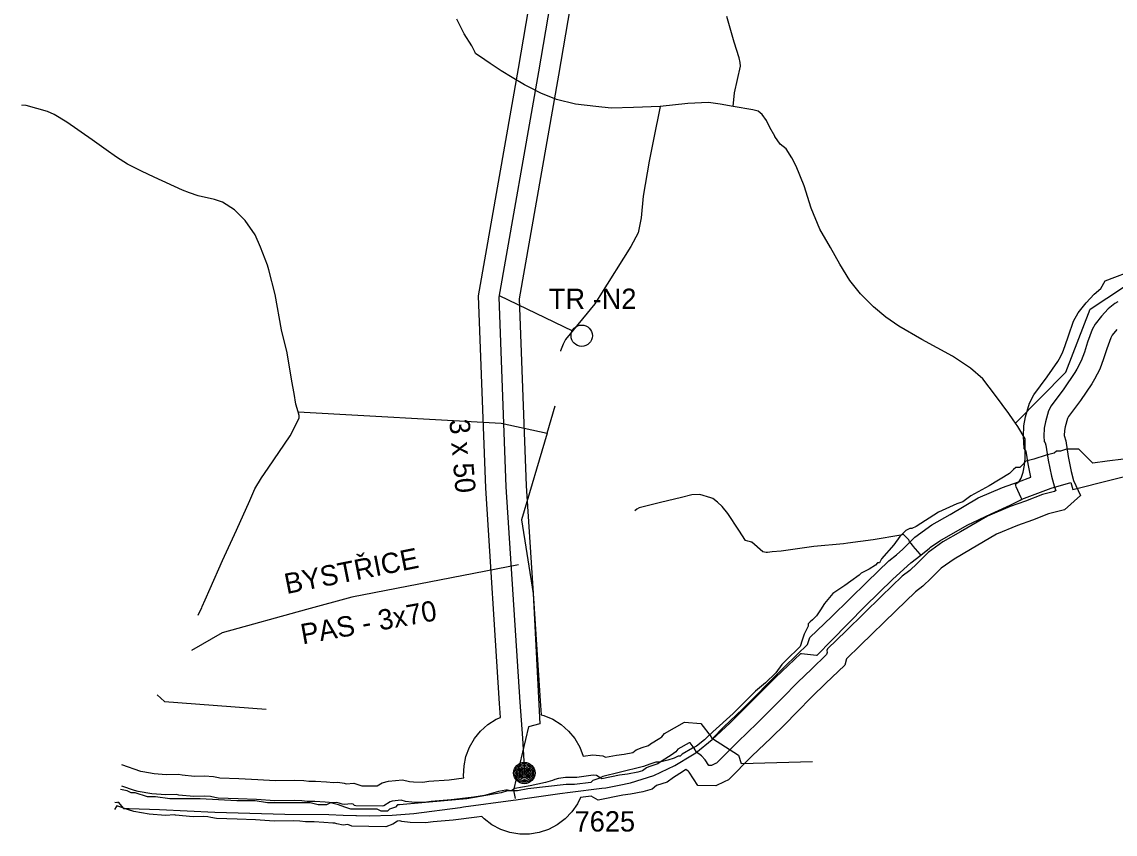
# Model space of a CAD drawing. Extents: x -439095 to -431527, y -1129525 to -1119219.
# Drawn here: x -438699 to -438161, y -1124403 to -1124004 of the extents above; entities that cross this region are included whole.
import ezdxf

# ---------------------------------------------------------------- set-up
doc = ezdxf.new("R2010")
doc.units = 0
for name, color, linetype in [('Hranice reseneho uzemi', 7, 'Continuous'), ('UZEMNI REZERVA', 7, 'Continuous'), ('Vrstva 11', 7, 'Continuous'), ('Vrstva 13', 7, 'Continuous'), ('Vrstva 19', 7, 'Continuous'), ('Vrstva 21', 7, 'Continuous'), ('Vrstva 58', 7, 'Continuous'), ('ZU', 7, 'Continuous')]:
    doc.layers.add(name, color=color, linetype=linetype)

msp = doc.modelspace()

# ---------------------------------------------------------------- linework, layer by layer
at = {"layer": 'Hranice reseneho uzemi'}
msp.add_line((-438464.02, -1124138.56), (-438428.03, -1124155.83), dxfattribs=at)
for points in [[(-438404.4, -1123792.3), (-438410.29, -1123829.14), (-438410.29, -1123829.15), (-438415.85, -1123861.97), (-438429.64, -1123939.97), (-438444.63, -1124028.49), (-438464.17, -1124139.38), (-438460.66, -1124232.64), (-438453.88, -1124338.49), (-438452.62, -1124356.08), (-438452.62, -1124356.09), (-438451.55, -1124372.99), (-438451.29, -1124373.35), (-438451.28, -1124373.5)], [(-438159.73, -1124141.57), (-438161.25, -1124142.38), (-438164.49, -1124145.06), (-438167.77, -1124148.6), (-438170.88, -1124152.51), (-438172.35, -1124155.27), (-438174.63, -1124161.5), (-438176.19, -1124166.38), (-438177.78, -1124170.67), (-438179.87, -1124174.71), (-438180.94, -1124176.42), (-438186.35, -1124184.31), (-438192.5, -1124192.7), (-438193.83, -1124195.21), (-438195.39, -1124200.58), (-438196.05, -1124203.67), (-438196.14, -1124207.6), (-438196, -1124210.23), (-438195.48, -1124210.94), (-438195.17, -1124212.06), (-438194.07, -1124219.42), (-438192.42, -1124227.33), (-438190.97, -1124232.78), (-438190.27, -1124234.31), (-438190.84, -1124234.82), (-438196.86, -1124236.34), (-438205.18, -1124239.55), (-438212.77, -1124242.22), (-438223.88, -1124246.96), (-438237.2, -1124254.75), (-438245.75, -1124259.66), (-438253.08, -1124264.93), (-438258.48, -1124270.33), (-438262.11, -1124273.73), (-438265.86, -1124276.55), (-438275.98, -1124286.4), (-438293.42, -1124303.41), (-438302.55, -1124312.28), (-438302.85, -1124313.1), (-438302.75, -1124314.02), (-438303, -1124314.98), (-438310.44, -1124322.14), (-438317.11, -1124328.6), (-438324.91, -1124336.52), (-438330.52, -1124342.17), (-438337.21, -1124348.83), (-438346.69, -1124357.9), (-438357.18, -1124368.4), (-438357.68, -1124368.64), (-438359.64, -1124369.6), (-438360.85, -1124369.58), (-438362.64, -1124366.81), (-438364.44, -1124364.77), (-438367.02, -1124363), (-438368.14, -1124361.12), (-438370.1, -1124358.5), (-438370.65, -1124358.46), (-438376.19, -1124361.59), (-438377.2, -1124362.79), (-438379.44, -1124364.45), (-438383.91, -1124367.24), (-438386.01, -1124368.79), (-438390.35, -1124370.16), (-438391.64, -1124370.67), (-438393.5, -1124372.16), (-438395.77, -1124372.84), (-438400.98, -1124373.87), (-438404.78, -1124374.31), (-438413.55, -1124376.09), (-438416.19, -1124374.51), (-438417.72, -1124374.37), (-438425.81, -1124375.5), (-438431.39, -1124375.53), (-438434.79, -1124375.92), (-438436.57, -1124376.42), (-438437.82, -1124377.04), (-438441.25, -1124377.9), (-438448.75, -1124379.6), (-438456.35, -1124380.91), (-438457.34, -1124381.58), (-438458.27, -1124382), (-438459.05, -1124381.94), (-438459.93, -1124381.67), (-438460.8, -1124381.66), (-438464.27, -1124382.33), (-438471.29, -1124384.36), (-438476.45, -1124385.16), (-438487.66, -1124386.53), (-438497.5, -1124387.28), (-438500.94, -1124387.74), (-438506.98, -1124387.67), (-438510.02, -1124387.25), (-438512.21, -1124386.7), (-438516.63, -1124387.2), (-438517.67, -1124387.47), (-438520.81, -1124389.41), (-438521.48, -1124389.66), (-438534.53, -1124389.49), (-438535.1, -1124389.26), (-438535.86, -1124388.65), (-438536.57, -1124388.43), (-438540.18, -1124388.78), (-438541.24, -1124388.54), (-438542.67, -1124388.07), (-438544.02, -1124387.84), (-438545.68, -1124387.9), (-438549.62, -1124387.61), (-438554.7, -1124387.34), (-438558.49, -1124387.33), (-438561.04, -1124386.93), (-438564.88, -1124386.78), (-438574.41, -1124386.96), (-438583.31, -1124386.37), (-438592.42, -1124385.91), (-438602.2, -1124385.64), (-438603.89, -1124385.39), (-438605.95, -1124384.9), (-438609.15, -1124384.74), (-438614.19, -1124384.76), (-438621.57, -1124384.15), (-438622.77, -1124383.86), (-438627.88, -1124384.09), (-438634.89, -1124383.53), (-438641.48, -1124382.36), (-438643.3, -1124381.86), (-438649.51, -1124379.72)], [(-438454.46, -1124270.9), (-438536.54, -1124286.77), (-438558.76, -1124292.96), (-438600.22, -1124304.31), (-438615.26, -1124312.96)]]:
    msp.add_lwpolyline(points, dxfattribs=at)
at = {"layer": 'UZEMNI REZERVA'}
for points in [[(-438348.9, -1124045.54), (-438355.36, -1124044.32), (-438361.03, -1124043.62), (-438371.16, -1124044.13), (-438384.78, -1124045.52), (-438397.98, -1124046.07), (-438408.99, -1124046.3), (-438416.44, -1124045.57), (-438426.48, -1124044.41), (-438435.87, -1124042.12), (-438443.49, -1124039.07), (-438449.57, -1124035.89), (-438451.55, -1124034.86), (-438457.67, -1124031.28), (-438463.03, -1124027.93), (-438467.95, -1124024.69), (-438468.49, -1124024.39), (-438471.13, -1124022.54), (-438475.63, -1124019.41), (-438475.9, -1124019), (-438476.32, -1124018), (-438477.44, -1124015.75), (-438481.23, -1124009.81), (-438484.76, -1124002.63)], [(-438206.98, -1124238.63), (-438207.31, -1124237.99), (-438209.68, -1124232.52), (-438210.03, -1124231.18), (-438208.35, -1124229.88), (-438207.24, -1124228.28), (-438206.27, -1124225.31), (-438205.6, -1124221.87), (-438205.39, -1124218.59), (-438205.38, -1124208.91), (-438208.95, -1124202.9), (-438211.18, -1124199.65), (-438213.44, -1124196.43), (-438219.91, -1124187.58), (-438226.22, -1124179.51), (-438232.16, -1124174.16), (-438241.15, -1124168.29), (-438256.12, -1124160.13), (-438267.39, -1124153.52), (-438273.87, -1124149.16), (-438279.88, -1124144.09), (-438286.38, -1124137.63), (-438291.57, -1124131.18), (-438296.51, -1124123.05), (-438301.01, -1124114.91), (-438306.3, -1124105.84), (-438310.53, -1124095.5), (-438313.97, -1124084.49), (-438317.97, -1124074.85), (-438320.09, -1124070.82), (-438322.85, -1124066.3), (-438325.76, -1124064.1), (-438328.43, -1124060.25), (-438328.45, -1124060.2), (-438328.48, -1124060.12), (-438330.86, -1124055.87), (-438332.48, -1124052.42), (-438334.63, -1124049.45), (-438336.71, -1124047.81), (-438339.25, -1124047.18), (-438348.9, -1124045.54), (-438348.28, -1124038.89), (-438345.38, -1124025.67), (-438345.49, -1124023.85), (-438345.92, -1124021.55), (-438348.43, -1124013.96), (-438352.09, -1124001.36)], [(-438611.98, -1124295.6), (-438611.01, -1124293.59), (-438610.3, -1124292.13), (-438610.02, -1124291.46), (-438608.61, -1124288.18), (-438606.17, -1124282.5), (-438600.02, -1124268.85), (-438593.18, -1124253.8), (-438586.66, -1124239.25), (-438584.12, -1124233.54), (-438580.97, -1124228.1), (-438577.55, -1124223.36), (-438566.79, -1124207.47), (-438562.46, -1124198.79), (-438562.34, -1124197.5), (-438562.81, -1124195.62), (-438563.95, -1124191.94), (-438564.89, -1124186.64), (-438565.95, -1124180.62), (-438568.31, -1124166.74), (-438571.02, -1124155.36), (-438574.11, -1124137.91), (-438577.28, -1124125.87), (-438577.88, -1124123.63), (-438581.44, -1124114.68), (-438584.01, -1124108.57), (-438588.98, -1124101.68), (-438594.14, -1124096.42), (-438600.12, -1124092.65), (-438604, -1124091.32), (-438611.99, -1124089.41), (-438616.32, -1124088), (-438619.76, -1124086.64), (-438633.77, -1124080.35), (-438639.91, -1124077.33), (-438646.77, -1124073.88), (-438652.27, -1124070.47), (-438657.36, -1124066.91), (-438664.23, -1124061.87), (-438676.61, -1124053.33), (-438682.81, -1124049.48), (-438686.13, -1124048.03), (-438696.57, -1124044.98), (-438698.73, -1124044.93), (-438698.75, -1124045.09)], [(-438384.78, -1124045.52), (-438388.19, -1124061.8), (-438390.22, -1124072.41), (-438393.2, -1124089.61), (-438394.14, -1124100.33), (-438395.74, -1124107.6), (-438399.34, -1124114.39), (-438414.52, -1124138.69), (-438416.92, -1124142.58), (-438431.45, -1124160.06), (-438432.62, -1124162.43), (-438433.86, -1124165.7), (-438433.84, -1124165.88)], [(-438210.06, -1124201.28), (-438185.4, -1124176.11), (-438173.41, -1124145.17), (-438156.99, -1124134.43), (-438095.98, -1124117.57)], [(-438562.81, -1124195.62), (-438463.1, -1124201.21), (-438440.37, -1124206.25), (-438436.53, -1124192.7)], [(-438440.37, -1124206.25), (-438453.11, -1124248.71), (-438447.29, -1124284.97), (-438443.96, -1124349.11), (-438449.54, -1124350.56), (-438456.94, -1124381.69), (-438456.2, -1124385.75)], [(-438653.02, -1124387.55), (-438651.91, -1124387.71), (-438651.67, -1124387.53), (-438651.46, -1124387.63), (-438648.8, -1124390.79), (-438646.01, -1124390.78), (-438631.05, -1124391.27), (-438603.82, -1124392.47), (-438569.46, -1124393.49), (-438547.87, -1124393.68), (-438540.72, -1124393.94), (-438534.45, -1124394.17), (-438534.19, -1124394.18), (-438528, -1124394.41), (-438516.72, -1124394.05), (-438505.99, -1124393.22), (-438483.22, -1124390.22), (-438481.54, -1124389.99), (-438457.2, -1124386.65), (-438455.64, -1124386.43), (-438452.59, -1124386), (-438434.26, -1124383.43), (-438429.15, -1124382.78), (-438413.51, -1124380.77), (-438411.63, -1124380.53), (-438405.01, -1124379.2), (-438399.39, -1124378.07), (-438387.96, -1124374.57), (-438377.57, -1124369.59), (-438368.91, -1124364.39), (-438367.27, -1124363.39), (-438359.31, -1124356.82), (-438350.39, -1124348.68), (-438329.27, -1124327.48), (-438328.12, -1124326.33), (-438315.69, -1124314.48), (-438315.29, -1124314.52), (-438308, -1124315.36), (-438307.67, -1124315.37), (-438300.65, -1124308.18), (-438284.26, -1124291.39), (-438270.47, -1124278.01), (-438261.49, -1124269.93), (-438256.66, -1124266.09), (-438252.43, -1124262.73), (-438251.88, -1124262.29), (-438247.26, -1124259.15), (-438233.92, -1124251.4), (-438222.01, -1124245.82), (-438212.65, -1124241.53), (-438207.77, -1124239.1), (-438206.98, -1124238.63), (-438192.51, -1124233.19), (-438182.87, -1124230.5), (-438181.97, -1124233.91), (-438144.24, -1124224.41)], [(-438256.66, -1124266.09), (-438256.98, -1124265.67), (-438260.37, -1124261.73), (-438260.5, -1124261.56), (-438260.62, -1124261.39), (-438260.77, -1124261.19), (-438262.14, -1124259.37), (-438262.34, -1124259.06), (-438262.45, -1124258.88), (-438262.57, -1124258.7), (-438264.3, -1124256.85), (-438265.18, -1124255.95), (-438266.51, -1124256.26), (-438280.11, -1124258.65), (-438292.59, -1124260.24), (-438294.75, -1124260.52), (-438309.24, -1124261.97), (-438325.35, -1124264.22), (-438329.8, -1124264.58), (-438332.08, -1124264.88), (-438332.78, -1124264.77), (-438334.34, -1124264.53), (-438339.73, -1124259.85), (-438339.86, -1124259.75), (-438340.39, -1124259.62), (-438341.72, -1124259.28), (-438342.88, -1124258.88), (-438346.22, -1124253.89), (-438351.6, -1124245.66), (-438354.34, -1124242.29), (-438356.62, -1124240.09), (-438358.91, -1124238.37), (-438359.86, -1124238.03), (-438365.3, -1124236.38), (-438369.28, -1124236.43), (-438374.42, -1124237.73), (-438384.75, -1124240.22), (-438395.24, -1124242.92), (-438396.36, -1124243.52), (-438397.23, -1124244.3)], [(-438632.18, -1124334.88), (-438628.53, -1124338.06), (-438578.66, -1124341.85)], [(-438359.18, -1124356.25), (-438346.28, -1124364.58), (-438345.05, -1124368.59), (-438309.93, -1124367.66)]]:
    msp.add_lwpolyline(points, dxfattribs=at)
at = {"layer": 'Vrstva 11'}
for radius in [5.25, 4.55, 3.85, 3.15, 2.45, 1.75, 1.05, 0.35]:
    msp.add_circle((-438451.64, -1124373.28), radius, dxfattribs=at)
at = {"layer": 'Vrstva 19'}
msp.add_circle((-438423.39, -1124158.28), 5.25, dxfattribs=at)
at = {"layer": 'Vrstva 58'}
for points in [[(-438176, -1124217), (-438179, -1124214), (-438180, -1124214), (-438182, -1124214), (-438185, -1124214), (-438188, -1124215), (-438190, -1124215), (-438191, -1124216), (-438195, -1124217), (-438201, -1124219), (-438205, -1124220), (-438207, -1124222), (-438208, -1124223), (-438210, -1124223), (-438211, -1124224), (-438213, -1124226), (-438223, -1124232), (-438232, -1124237), (-438236, -1124240), (-438239, -1124241), (-438248, -1124245), (-438259, -1124252), (-438261, -1124253), (-438262, -1124253), (-438264, -1124254), (-438264, -1124254), (-438267, -1124257), (-438270, -1124261), (-438276, -1124268), (-438277, -1124270), (-438278, -1124270), (-438279, -1124271), (-438282, -1124273), (-438284, -1124274), (-438286, -1124275), (-438287, -1124276), (-438291, -1124279), (-438294, -1124281), (-438300, -1124285), (-438304, -1124290), (-438306, -1124293), (-438308, -1124296), (-438310, -1124298), (-438311, -1124299), (-438312, -1124300), (-438312, -1124301), (-438314, -1124305), (-438315, -1124308), (-438316, -1124311), (-438316, -1124311), (-438317, -1124312), (-438322, -1124317), (-438325, -1124320), (-438328, -1124324), (-438333, -1124329), (-438338, -1124333), (-438339, -1124334), (-438346, -1124341), (-438349, -1124344), (-438359, -1124353), (-438362, -1124356), (-438363, -1124357), (-438363, -1124357), (-438367, -1124360), (-438369, -1124361), (-438374, -1124364), (-438374, -1124364), (-438375, -1124365), (-438376, -1124365), (-438378, -1124366), (-438381, -1124367), (-438385, -1124368), (-438387, -1124368), (-438390, -1124369), (-438393, -1124370), (-438405, -1124373), (-438413, -1124375), (-438415, -1124376), (-438418, -1124377), (-438419, -1124378), (-438427, -1124379), (-438431, -1124379), (-438450, -1124381), (-438455, -1124382), (-438460, -1124382), (-438463, -1124383), (-438480, -1124386), (-438491, -1124387), (-438513, -1124389), (-438514, -1124389), (-438515, -1124390)], [(-438157, -1124219), (-438165, -1124220), (-438172, -1124221), (-438173, -1124220), (-438176, -1124217)], [(-438515, -1124390), (-438518, -1124391), (-438519, -1124392), (-438522, -1124392), (-438524, -1124391), (-438527, -1124391), (-438529, -1124391), (-438534, -1124391), (-438537, -1124391), (-438540, -1124390), (-438543, -1124389), (-438547, -1124388), (-438549, -1124389), (-438552, -1124389), (-438553, -1124389), (-438557, -1124388), (-438571, -1124388), (-438578, -1124388), (-438584, -1124387), (-438589, -1124387), (-438593, -1124387), (-438611, -1124386), (-438613, -1124386), (-438617, -1124386), (-438621, -1124386), (-438623, -1124386), (-438626, -1124386), (-438633, -1124385), (-438637, -1124385), (-438643, -1124383), (-438645, -1124383), (-438647, -1124382), (-438650.24, -1124381.35)]]:
    msp.add_lwpolyline(points, dxfattribs=at)
at = {"layer": 'ZU'}
for points in [[(-438463.37, -1124345.98), (-438463.86, -1124339.17), (-438470.65, -1124233.15), (-438474.2, -1124138.69), (-438454.48, -1124026.79), (-438439.49, -1123938.26), (-438425.7, -1123860.26), (-438420.16, -1123827.52), (-438415.66, -1123799.41)], [(-438410.09, -1123886.85), (-438419.79, -1123941.67), (-438434.77, -1124030.2), (-438454.13, -1124140.07), (-438450.67, -1124232.14), (-438443.91, -1124337.81), (-438443.42, -1124344.63)], [(-438422.75, -1124364.97), (-438417.96, -1124364.31), (-438413.01, -1124364.76), (-438411.74, -1124365.52), (-438406.35, -1124364.43), (-438402.53, -1124363.98), (-438398.22, -1124363.13), (-438396.72, -1124361.92), (-438393.7, -1124360.73), (-438390.61, -1124359.76), (-438389.54, -1124358.96), (-438385.07, -1124356.18), (-438384.1, -1124355.45), (-438382.68, -1124353.77), (-438372.94, -1124348.27), (-438364.83, -1124348.86), (-438359.82, -1124355.55), (-438359.55, -1124356), (-438359.18, -1124356.25), (-438353.68, -1124350.75), (-438344.19, -1124341.67), (-438337.6, -1124335.1), (-438332.02, -1124329.49), (-438324.15, -1124321.5), (-438317.39, -1124314.95), (-438312.43, -1124310.17), (-438311.16, -1124306.7), (-438300.4, -1124296.24), (-438282.96, -1124279.24), (-438272.38, -1124268.94), (-438268.55, -1124266.06), (-438265.44, -1124263.14), (-438259.58, -1124257.28), (-438251.17, -1124251.24), (-438242.21, -1124246.1), (-438228.38, -1124238.01), (-438216.4, -1124232.89), (-438208.64, -1124230.17), (-438202.53, -1124227.81), (-438203.92, -1124221.18), (-438204.83, -1124215.1), (-438205.83, -1124213.74), (-438206.15, -1124207.75), (-438206.03, -1124202.5), (-438205.09, -1124198.14), (-438203.15, -1124191.43), (-438201, -1124187.37), (-438194.51, -1124178.53), (-438189.31, -1124170.94), (-438188.56, -1124169.75), (-438186.94, -1124166.62), (-438185.65, -1124163.12), (-438184.09, -1124158.26), (-438181.5, -1124151.18), (-438179.28, -1124147), (-438175.36, -1124142.08), (-438171.37, -1124137.78), (-438168.13, -1124135.09), (-438166.03, -1124131.26), (-438150.49, -1124125.35)], [(-438160.18, -1124155.12), (-438162.48, -1124158.02), (-438163.2, -1124159.36), (-438165.17, -1124164.74), (-438166.73, -1124169.64), (-438168.62, -1124174.72), (-438171.18, -1124179.67), (-438172.57, -1124181.9), (-438178.19, -1124190.09), (-438184, -1124198.03), (-438184.51, -1124198.99), (-438185.69, -1124203.02), (-438186.07, -1124204.84), (-438186.13, -1124207.24), (-438185.37, -1124209.98), (-438184.22, -1124217.66), (-438182.69, -1124225.02), (-438181.52, -1124229.39), (-438178.11, -1124236.85), (-438186.01, -1124243.91), (-438193.83, -1124245.89), (-438201.72, -1124248.93), (-438209.14, -1124251.55), (-438219.38, -1124255.91), (-438232.19, -1124263.4), (-438240.33, -1124268.08), (-438246.58, -1124272.58), (-438251.52, -1124277.52), (-438255.67, -1124281.4), (-438259.34, -1124284.16), (-438269, -1124293.56), (-438286.44, -1124310.58), (-438293.24, -1124317.18), (-438294.03, -1124320.23), (-438303.49, -1124329.33), (-438310.07, -1124335.7), (-438317.8, -1124343.55), (-438323.44, -1124349.24), (-438330.23, -1124355.99), (-438339.7, -1124365.05), (-438351.31, -1124376.68), (-438353.32, -1124377.64), (-438357.4, -1124379.64), (-438366.35, -1124379.49), (-438370.63, -1124372.87), (-438371.12, -1124372.32), (-438372.23, -1124371.55), (-438373.81, -1124372.72), (-438378.28, -1124375.52), (-438381.41, -1124377.82), (-438386.64, -1124379.47), (-438388.77, -1124381.18), (-438393.36, -1124382.56), (-438399.43, -1124383.76), (-438403.21, -1124384.19), (-438415.36, -1124386.66), (-438418.78, -1124384.61), (-438424.08, -1124385.36)], [(-438481.37, -1124375.69), (-438481.5, -1124374.64), (-438481.3, -1124369.81), (-438480.34, -1124365.08), (-438478.62, -1124360.57), (-438476.21, -1124356.39), (-438473.16, -1124352.65), (-438469.54, -1124349.45), (-438465.46, -1124346.87), (-438463.37, -1124345.98)], [(-438443.42, -1124344.63), (-438442.02, -1124344.97), (-438437.58, -1124346.87), (-438433.5, -1124349.45), (-438429.88, -1124352.65), (-438426.83, -1124356.39), (-438424.42, -1124360.57), (-438422.75, -1124364.97)], [(-438649.79, -1124369.05), (-438640.34, -1124372.3), (-438639.28, -1124372.59), (-438633.61, -1124373.6), (-438627.71, -1124374.07), (-438621.8, -1124373.81), (-438619.97, -1124374.25), (-438613.8, -1124374.76), (-438608.92, -1124374.74), (-438604.53, -1124374.96), (-438602, -1124375.56), (-438601.33, -1124375.66), (-438592.03, -1124375.92), (-438582.73, -1124376.39), (-438574.17, -1124376.95), (-438564.78, -1124376.78), (-438560.07, -1124376.96), (-438557.7, -1124377.33), (-438554.42, -1124377.34), (-438548.99, -1124377.63), (-438545.49, -1124377.89), (-438543.35, -1124377.81), (-438540.26, -1124378.34), (-438539.31, -1124378.65), (-438535.53, -1124378.28), (-438531.51, -1124379.53), (-438524, -1124379.63), (-438521.64, -1124378.17), (-438518.46, -1124377.34), (-438511.53, -1124376.56), (-438508.11, -1124377.42), (-438506.23, -1124377.68), (-438501.55, -1124377.73), (-438498.54, -1124377.33), (-438488.65, -1124376.58), (-438481.37, -1124375.69)], [(-438424.08, -1124385.36), (-438425.54, -1124388.43), (-438428.28, -1124392.4), (-438431.63, -1124395.89), (-438435.49, -1124398.79), (-438439.76, -1124401.03), (-438444.34, -1124402.56), (-438449.11, -1124403.33), (-438453.93, -1124403.33), (-438458.7, -1124402.56), (-438463.28, -1124401.03), (-438467.55, -1124398.79), (-438471.41, -1124395.89), (-438472.57, -1124394.68)], [(-438472.57, -1124394.68), (-438475.08, -1124395.07), (-438486.67, -1124396.48), (-438496.46, -1124397.23), (-438500.33, -1124397.75), (-438507.73, -1124397.66), (-438511.93, -1124397.08), (-438512.89, -1124396.84), (-438514.02, -1124396.97), (-438516.39, -1124398.43), (-438519.74, -1124399.68), (-438536.53, -1124399.46), (-438538.51, -1124398.67), (-438540.82, -1124398.89), (-438543.91, -1124398.19), (-438544.86, -1124397.88), (-438545.87, -1124397.91), (-438550.25, -1124397.59), (-438554.98, -1124397.34), (-438559.28, -1124397.33), (-438562.01, -1124396.9), (-438564.98, -1124396.78), (-438574.65, -1124396.97), (-438583.89, -1124396.35), (-438592.81, -1124395.9), (-438603.07, -1124395.62), (-438605.78, -1124395.22), (-438607.37, -1124394.84), (-438609.38, -1124394.74), (-438614.58, -1124394.76), (-438623.17, -1124394.05), (-438623.74, -1124393.91), (-438628.05, -1124394.11), (-438636.17, -1124393.46), (-438643.68, -1124392.13), (-438646.26, -1124391.42), (-438652.06, -1124389.42), (-438652.32, -1124389.89), (-438653.13, -1124391.22)]]:
    msp.add_lwpolyline(points, dxfattribs=at)

# ---------------------------------------------------------------- texts
at = {"layer": 'Vrstva 13'}
for s, rotation, p in [('3 x 50', 274.994, (-438488.56, -1124199.69)), ('BYSTŘICE', 11.2823, (-438568.55, -1124285.32)), ('PAS - 3x70', 10.1668, (-438560.68, -1124310.05))]:
    msp.add_text(s, height=10, rotation=rotation, dxfattribs=at).set_placement(p)
msp.add_text('7625', height=10, dxfattribs=at).set_placement((-438426.92, -1124402.06))
at = {"layer": 'Vrstva 21'}
msp.add_text('TR -N2', height=10, dxfattribs=at).set_placement((-438439.59, -1124145.1))

doc.saveas('drawing.dxf')
